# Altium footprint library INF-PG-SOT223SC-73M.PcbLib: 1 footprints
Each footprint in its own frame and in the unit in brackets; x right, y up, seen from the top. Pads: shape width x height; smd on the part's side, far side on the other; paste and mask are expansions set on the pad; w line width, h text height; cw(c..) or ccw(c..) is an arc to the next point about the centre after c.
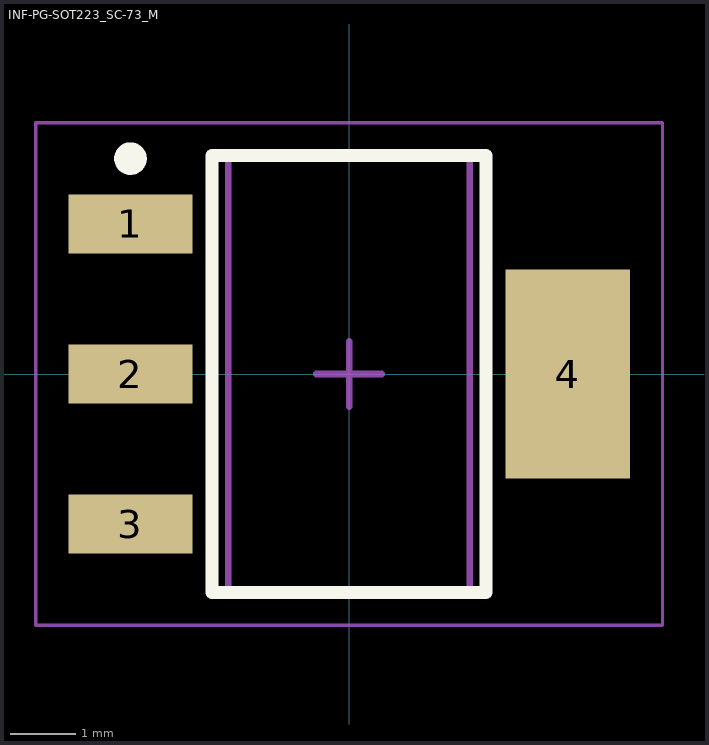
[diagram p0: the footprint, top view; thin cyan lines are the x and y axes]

## INF-PG-SOT223_SC-73_M [mm] "SOT223, 4-Leads, Body 6.5x3.5mm, Pitch 2.3mm, IPC Low Density"
height 1.8
pads (4):
  rect 1.9x0.9 smd: 1(-3.35,2.3) 2(-3.35,0) 3(-3.35,-2.3)
  rect 1.9x3.2 smd: 4(3.35,0)
Top Overlay:
  circle w0.25: c-3.35,3.3 r0.125
  lines w0.2: -2.1,-3.35 -2.1,3.35 2.1,3.35 2.1,-3.35 -2.1,-3.35
Mechanical 13:
  lines w0.1: -1.85,-3.35 -1.85,3.35 1.85,3.35 1.85,-3.35 -1.85,-3.35
Mechanical 15:
  lines w0.05: -4.8,-3.85 -4.8,3.85 4.8,3.85 4.8,-3.85 -4.8,-3.85
  lines w0.1: -0.5,0 0.5,0 ; 0,-0.5 0,0.5
3D body: height 1.8, standoff 0.1, extent -1.85,-3.35 1.85,3.35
